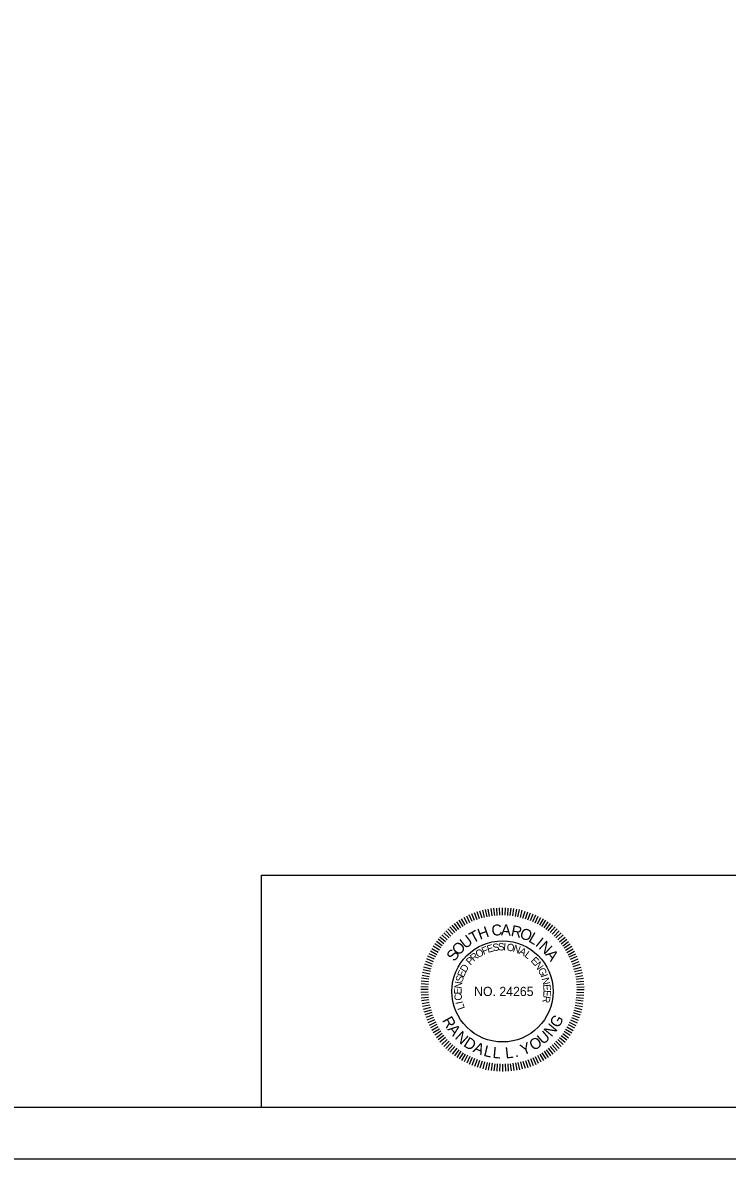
# Model space of a CAD drawing. Extents: x 8134 to 11793, y 3225 to 13425.
# Drawn here: x 10879 to 11221, y 5500 to 6050 of the extents above; entities that cross this region are included whole.
import ezdxf

# ---------------------------------------------------------------- set-up
doc = ezdxf.new("R2010")
doc.units = 0
for name, color, linetype in [('RD_SHT_Bndy', 7, 'Continuous'), ('RD_SHT_IplotShp', 7, 'Continuous'), ('RD_TX_PEShield', 7, 'Continuous')]:
    doc.layers.add(name, color=color, linetype=linetype)

msp = doc.modelspace()

# ---------------------------------------------------------------- linework, layer by layer
at = {"layer": 'RD_SHT_Bndy'}
for p, q in [((10995.01, 5637.45), (11757.6, 5637.45)), ((10995.01, 5525), (10995.01, 5637.45)), ((11760, 5500), (10000, 5500)), ((11760, 5500), (10000, 5500))]:
    msp.add_line(p, q, dxfattribs=at)
msp.add_lwpolyline([(10082.6, 6575), (11757.6, 6575), (11757.6, 5525), (10082.6, 5525)], close=True, dxfattribs=at)
at = {"layer": 'RD_SHT_IplotShp'}
msp.add_lwpolyline([(9981.4, 6600), (11777.4, 6600), (11777.4, 5500), (9981.4, 5500)], close=True, dxfattribs=at)
at = {"layer": 'RD_TX_PEShield'}
for p, q in [((11105.5, 5617.56), (11104.88, 5621.06)), ((11105.5, 5617.56), (11104.88, 5621.06)), ((11106.74, 5617.75), (11106.24, 5621.28)), ((11106.74, 5617.75), (11106.24, 5621.28)), ((11107.98, 5617.95), (11107.61, 5621.49)), ((11107.98, 5617.95), (11107.61, 5621.49)), ((11109.24, 5618.02), (11108.99, 5621.56)), ((11109.24, 5618.02), (11108.99, 5621.56)), ((11110.49, 5618.08), (11110.37, 5621.64)), ((11110.49, 5618.08), (11110.37, 5621.64)), ((11111.75, 5618.15), (11111.75, 5621.71)), ((11111.75, 5618.15), (11111.75, 5621.71)), ((11113.01, 5618.08), (11113.13, 5621.64)), ((11113.01, 5618.08), (11113.13, 5621.64)), ((11114.26, 5618.02), (11114.51, 5621.56)), ((11114.26, 5618.02), (11114.51, 5621.56)), ((11115.52, 5617.95), (11115.89, 5621.49)), ((11115.52, 5617.95), (11115.89, 5621.49)), ((11116.76, 5617.75), (11117.26, 5621.28)), ((11116.76, 5617.75), (11117.26, 5621.28)), ((11118, 5617.56), (11118.62, 5621.06)), ((11118, 5617.56), (11118.62, 5621.06)), ((11092.67, 5612.63), (11090.79, 5615.65)), ((11092.67, 5612.63), (11090.79, 5615.65)), ((11093.73, 5613.32), (11091.95, 5616.4)), ((11093.73, 5613.32), (11091.95, 5616.4)), ((11094.85, 5613.89), (11093.18, 5617.03)), ((11094.85, 5613.89), (11093.18, 5617.03)), ((11095.97, 5614.46), (11094.41, 5617.66)), ((11095.97, 5614.46), (11094.41, 5617.66)), ((11097.09, 5615.03), (11095.64, 5618.29)), ((11097.09, 5615.03), (11095.64, 5618.29)), ((11098.26, 5615.48), (11096.93, 5618.78)), ((11098.26, 5615.48), (11096.93, 5618.78)), ((11099.44, 5615.93), (11098.22, 5619.28)), ((11099.44, 5615.93), (11098.22, 5619.28)), ((11100.61, 5616.38), (11099.51, 5619.77)), ((11100.61, 5616.38), (11099.51, 5619.77)), ((11101.83, 5616.71), (11100.85, 5620.13)), ((11101.83, 5616.71), (11100.85, 5620.13)), ((11103.04, 5617.04), (11102.18, 5620.49)), ((11103.04, 5617.04), (11102.18, 5620.49)), ((11104.26, 5617.36), (11103.52, 5620.84)), ((11104.26, 5617.36), (11103.52, 5620.84)), ((11119.24, 5617.36), (11119.98, 5620.84)), ((11119.24, 5617.36), (11119.98, 5620.84)), ((11119.24, 5617.36), (11119.98, 5620.84)), ((11120.46, 5617.04), (11121.32, 5620.49)), ((11120.46, 5617.04), (11121.32, 5620.49)), ((11120.46, 5617.04), (11121.32, 5620.49)), ((11121.67, 5616.71), (11122.65, 5620.13)), ((11121.67, 5616.71), (11122.65, 5620.13)), ((11121.67, 5616.71), (11122.65, 5620.13)), ((11122.89, 5616.38), (11123.99, 5619.77)), ((11122.89, 5616.38), (11123.99, 5619.77)), ((11122.89, 5616.38), (11123.99, 5619.77)), ((11124.06, 5615.93), (11125.28, 5619.28)), ((11124.06, 5615.93), (11125.28, 5619.28)), ((11124.06, 5615.93), (11125.28, 5619.28)), ((11125.24, 5615.48), (11126.57, 5618.78)), ((11125.24, 5615.48), (11126.57, 5618.78)), ((11125.24, 5615.48), (11126.57, 5618.78)), ((11126.41, 5615.03), (11127.86, 5618.29)), ((11126.41, 5615.03), (11127.86, 5618.29)), ((11126.41, 5615.03), (11127.86, 5618.29)), ((11127.53, 5614.46), (11129.09, 5617.66)), ((11127.53, 5614.46), (11129.09, 5617.66)), ((11127.53, 5614.46), (11129.09, 5617.66)), ((11128.65, 5613.89), (11130.32, 5617.03)), ((11128.65, 5613.89), (11130.32, 5617.03)), ((11128.65, 5613.89), (11130.32, 5617.03)), ((11129.77, 5613.32), (11131.55, 5616.4)), ((11129.77, 5613.32), (11131.55, 5616.4)), ((11129.77, 5613.32), (11131.55, 5616.4)), ((11130.83, 5612.63), (11132.71, 5615.65)), ((11130.83, 5612.63), (11132.71, 5615.65)), ((11130.83, 5612.63), (11132.71, 5615.65)), ((11086.74, 5608), (11084.27, 5610.56)), ((11086.74, 5608), (11084.27, 5610.56)), ((11087.63, 5608.89), (11085.25, 5611.54)), ((11087.63, 5608.89), (11085.25, 5611.54)), ((11088.61, 5609.68), (11086.32, 5612.41)), ((11088.61, 5609.68), (11086.32, 5612.41)), ((11089.59, 5610.47), (11087.4, 5613.28)), ((11089.59, 5610.47), (11087.4, 5613.28)), ((11090.56, 5611.27), (11088.47, 5614.15)), ((11090.56, 5611.27), (11088.47, 5614.15)), ((11091.62, 5611.95), (11089.63, 5614.9)), ((11091.62, 5611.95), (11089.63, 5614.9)), ((11131.88, 5611.95), (11133.87, 5614.9)), ((11131.88, 5611.95), (11133.87, 5614.9)), ((11131.88, 5611.95), (11133.87, 5614.9)), ((11132.94, 5611.27), (11135.03, 5614.15)), ((11132.94, 5611.27), (11135.03, 5614.15)), ((11132.94, 5611.27), (11135.03, 5614.15)), ((11133.91, 5610.47), (11136.1, 5613.28)), ((11133.91, 5610.47), (11136.1, 5613.28)), ((11133.91, 5610.47), (11136.1, 5613.28)), ((11134.89, 5609.68), (11137.18, 5612.41)), ((11134.89, 5609.68), (11137.18, 5612.41)), ((11134.89, 5609.68), (11137.18, 5612.41)), ((11135.87, 5608.89), (11138.25, 5611.54)), ((11135.87, 5608.89), (11138.25, 5611.54)), ((11135.87, 5608.89), (11138.25, 5611.54)), ((11136.76, 5608), (11139.23, 5610.56)), ((11136.76, 5608), (11139.23, 5610.56)), ((11136.76, 5608), (11139.23, 5610.56)), ((11082.59, 5603.29), (11079.71, 5605.38)), ((11082.59, 5603.29), (11079.71, 5605.38)), ((11083.38, 5604.27), (11080.58, 5606.46)), ((11083.38, 5604.27), (11080.58, 5606.46)), ((11084.17, 5605.25), (11081.45, 5607.53)), ((11084.17, 5605.25), (11081.45, 5607.53)), ((11084.96, 5606.22), (11082.32, 5608.6)), ((11084.96, 5606.22), (11082.32, 5608.6)), ((11085.85, 5607.11), (11083.3, 5609.58)), ((11085.85, 5607.11), (11083.3, 5609.58)), ((11137.65, 5607.11), (11140.2, 5609.58)), ((11137.65, 5607.11), (11140.2, 5609.58)), ((11137.65, 5607.11), (11140.2, 5609.58)), ((11138.54, 5606.22), (11141.18, 5608.6)), ((11138.54, 5606.22), (11141.18, 5608.6)), ((11138.54, 5606.22), (11141.18, 5608.6)), ((11139.33, 5605.25), (11142.05, 5607.53)), ((11139.33, 5605.25), (11142.05, 5607.53)), ((11139.33, 5605.25), (11142.05, 5607.53)), ((11140.12, 5604.27), (11142.92, 5606.46)), ((11140.12, 5604.27), (11142.92, 5606.46)), ((11140.12, 5604.27), (11142.92, 5606.46)), ((11140.91, 5603.29), (11143.79, 5605.38)), ((11140.91, 5603.29), (11143.79, 5605.38)), ((11140.91, 5603.29), (11143.79, 5605.38)), ((11079.39, 5597.89), (11076.2, 5599.44)), ((11079.39, 5597.89), (11076.2, 5599.44)), ((11079.96, 5599.01), (11076.82, 5600.67)), ((11079.96, 5599.01), (11076.82, 5600.67)), ((11080.53, 5600.13), (11077.45, 5601.91)), ((11080.53, 5600.13), (11077.45, 5601.91)), ((11081.22, 5601.18), (11078.2, 5603.07)), ((11081.22, 5601.18), (11078.2, 5603.07)), ((11081.9, 5602.24), (11078.96, 5604.22)), ((11081.9, 5602.24), (11078.96, 5604.22)), ((11141.6, 5602.24), (11144.54, 5604.22)), ((11141.6, 5602.24), (11144.54, 5604.22)), ((11141.6, 5602.24), (11144.54, 5604.22)), ((11142.28, 5601.18), (11145.3, 5603.07)), ((11142.28, 5601.18), (11145.3, 5603.07)), ((11142.28, 5601.18), (11145.3, 5603.07)), ((11142.97, 5600.13), (11146.05, 5601.91)), ((11142.97, 5600.13), (11146.05, 5601.91)), ((11142.97, 5600.13), (11146.05, 5601.91)), ((11143.54, 5599.01), (11146.68, 5600.67)), ((11143.54, 5599.01), (11146.68, 5600.67)), ((11143.54, 5599.01), (11146.68, 5600.67)), ((11144.11, 5597.89), (11147.3, 5599.44)), ((11144.11, 5597.89), (11147.3, 5599.44)), ((11144.11, 5597.89), (11147.3, 5599.44)), ((11077.47, 5593.24), (11074.08, 5594.34)), ((11077.47, 5593.24), (11074.08, 5594.34)), ((11077.92, 5594.42), (11074.58, 5595.63)), ((11077.92, 5594.42), (11074.58, 5595.63)), ((11078.37, 5595.59), (11075.07, 5596.92)), ((11078.37, 5595.59), (11075.07, 5596.92)), ((11078.82, 5596.76), (11075.57, 5598.21)), ((11078.82, 5596.76), (11075.57, 5598.21)), ((11144.68, 5596.76), (11147.93, 5598.21)), ((11144.68, 5596.76), (11147.93, 5598.21)), ((11144.68, 5596.76), (11147.93, 5598.21)), ((11145.13, 5595.59), (11148.43, 5596.92)), ((11145.13, 5595.59), (11148.43, 5596.92)), ((11145.13, 5595.59), (11148.43, 5596.92)), ((11145.58, 5594.42), (11148.92, 5595.63)), ((11145.58, 5594.42), (11148.92, 5595.63)), ((11145.58, 5594.42), (11148.92, 5595.63)), ((11146.03, 5593.24), (11149.42, 5594.34)), ((11146.03, 5593.24), (11149.42, 5594.34)), ((11146.03, 5593.24), (11149.42, 5594.34)), ((11076.3, 5588.36), (11072.79, 5588.97)), ((11076.3, 5588.36), (11072.79, 5588.97)), ((11076.49, 5589.6), (11073.01, 5590.34)), ((11076.49, 5589.6), (11073.01, 5590.34)), ((11076.82, 5590.81), (11073.37, 5591.67)), ((11076.82, 5590.81), (11073.37, 5591.67)), ((11077.14, 5592.03), (11073.73, 5593.01)), ((11077.14, 5592.03), (11073.73, 5593.01)), ((11146.36, 5592.03), (11149.77, 5593.01)), ((11146.36, 5592.03), (11149.77, 5593.01)), ((11146.36, 5592.03), (11149.77, 5593.01)), ((11146.68, 5590.81), (11150.13, 5591.67)), ((11146.68, 5590.81), (11150.13, 5591.67)), ((11146.68, 5590.81), (11150.13, 5591.67)), ((11147.01, 5589.6), (11150.49, 5590.34)), ((11147.01, 5589.6), (11150.49, 5590.34)), ((11147.01, 5589.6), (11150.49, 5590.34)), ((11147.2, 5588.36), (11150.71, 5588.97)), ((11147.2, 5588.36), (11150.71, 5588.97)), ((11147.2, 5588.36), (11150.71, 5588.97)), ((11075.77, 5583.36), (11072.22, 5583.48)), ((11075.77, 5583.36), (11072.22, 5583.48)), ((11075.84, 5584.62), (11072.29, 5584.86)), ((11075.84, 5584.62), (11072.29, 5584.86)), ((11075.9, 5585.87), (11072.36, 5586.24)), ((11075.9, 5585.87), (11072.36, 5586.24)), ((11076.1, 5587.11), (11072.58, 5587.61)), ((11076.1, 5587.11), (11072.58, 5587.61)), ((11147.4, 5587.11), (11150.92, 5587.61)), ((11147.4, 5587.11), (11150.92, 5587.61)), ((11147.4, 5587.11), (11150.92, 5587.61)), ((11147.6, 5585.87), (11151.14, 5586.24)), ((11147.6, 5585.87), (11151.14, 5586.24)), ((11147.6, 5585.87), (11151.14, 5586.24)), ((11147.66, 5584.62), (11151.21, 5584.86)), ((11147.66, 5584.62), (11151.21, 5584.86)), ((11147.66, 5584.62), (11151.21, 5584.86)), ((11147.73, 5583.36), (11151.28, 5583.48)), ((11147.73, 5583.36), (11151.28, 5583.48)), ((11147.73, 5583.36), (11151.28, 5583.48)), ((11075.7, 5582.1), (11072.14, 5582.1)), ((11075.7, 5582.1), (11072.14, 5582.1)), ((11075.77, 5580.85), (11072.22, 5580.72)), ((11075.77, 5580.85), (11072.22, 5580.72)), ((11075.84, 5579.59), (11072.29, 5579.34)), ((11075.84, 5579.59), (11072.29, 5579.34)), ((11075.9, 5578.34), (11072.36, 5577.96)), ((11075.9, 5578.34), (11072.36, 5577.96)), ((11076.1, 5577.09), (11072.58, 5576.6)), ((11076.1, 5577.09), (11072.58, 5576.6)), ((11147.27, 5577.11), (11150.78, 5576.62)), ((11147.27, 5577.11), (11150.78, 5576.62)), ((11147.4, 5578.36), (11150.92, 5577.99)), ((11147.4, 5578.36), (11150.92, 5577.99)), ((11147.53, 5579.6), (11151.07, 5579.35)), ((11147.53, 5579.6), (11151.07, 5579.35)), ((11147.66, 5580.85), (11151.21, 5580.73)), ((11147.66, 5580.85), (11151.21, 5580.73)), ((11147.79, 5582.1), (11151.35, 5582.1)), ((11147.79, 5582.1), (11151.35, 5582.1)), ((11147.79, 5582.1), (11151.35, 5582.1)), ((11076.3, 5575.85), (11072.79, 5575.24)), ((11076.3, 5575.85), (11072.79, 5575.24)), ((11076.49, 5574.61), (11073.01, 5573.87)), ((11076.49, 5574.61), (11073.01, 5573.87)), ((11076.82, 5573.39), (11073.37, 5572.53)), ((11076.82, 5573.39), (11073.37, 5572.53)), ((11077.14, 5572.18), (11073.73, 5571.2)), ((11077.14, 5572.18), (11073.73, 5571.2)), ((11146.36, 5572.18), (11149.77, 5571.2)), ((11146.36, 5572.18), (11149.77, 5571.2)), ((11146.68, 5573.39), (11150.13, 5572.53)), ((11146.68, 5573.39), (11150.13, 5572.53)), ((11147.01, 5574.61), (11150.49, 5573.87)), ((11147.01, 5574.61), (11150.49, 5573.87)), ((11147.14, 5575.86), (11150.63, 5575.25)), ((11147.14, 5575.86), (11150.63, 5575.25)), ((11077.47, 5570.97), (11074.08, 5569.87)), ((11077.92, 5569.79), (11074.58, 5568.57)), ((11077.92, 5569.79), (11074.58, 5568.57)), ((11078.37, 5568.62), (11075.07, 5567.29)), ((11078.37, 5568.62), (11075.07, 5567.29)), ((11078.82, 5567.44), (11075.57, 5566)), ((11078.82, 5567.44), (11075.57, 5566)), ((11079.39, 5566.32), (11076.2, 5564.76)), ((11079.39, 5566.32), (11076.2, 5564.76)), ((11144.11, 5566.32), (11147.3, 5564.76)), ((11144.11, 5566.32), (11147.3, 5564.76)), ((11144.68, 5567.44), (11147.93, 5566)), ((11144.68, 5567.44), (11147.93, 5566)), ((11145.13, 5568.62), (11148.43, 5567.29)), ((11145.13, 5568.62), (11148.43, 5567.29)), ((11145.58, 5569.79), (11148.92, 5568.57)), ((11145.58, 5569.79), (11148.92, 5568.57)), ((11146.03, 5570.97), (11149.42, 5569.87)), ((11146.03, 5570.97), (11149.42, 5569.87)), ((11079.96, 5565.2), (11076.82, 5563.53)), ((11079.96, 5565.2), (11076.82, 5563.53)), ((11080.53, 5564.08), (11077.45, 5562.3)), ((11080.53, 5564.08), (11077.45, 5562.3)), ((11081.22, 5563.03), (11078.2, 5561.14)), ((11081.22, 5563.03), (11078.2, 5561.14)), ((11081.9, 5561.97), (11078.96, 5559.98)), ((11081.9, 5561.97), (11078.96, 5559.98)), ((11082.59, 5560.92), (11079.71, 5558.82)), ((11082.59, 5560.92), (11079.71, 5558.82)), ((11140.91, 5560.92), (11143.79, 5558.82)), ((11140.91, 5560.92), (11143.79, 5558.82)), ((11141.6, 5561.97), (11144.54, 5559.98)), ((11141.6, 5561.97), (11144.54, 5559.98)), ((11142.28, 5563.03), (11145.3, 5561.14)), ((11142.28, 5563.03), (11145.3, 5561.14)), ((11142.97, 5564.08), (11146.05, 5562.3)), ((11142.97, 5564.08), (11146.05, 5562.3)), ((11143.54, 5565.2), (11146.68, 5563.53)), ((11143.54, 5565.2), (11146.68, 5563.53)), ((11083.38, 5559.94), (11080.58, 5557.75)), ((11083.38, 5559.94), (11080.58, 5557.75)), ((11084.17, 5558.96), (11081.45, 5556.68)), ((11084.17, 5558.96), (11081.45, 5556.68)), ((11084.96, 5557.99), (11082.32, 5555.6)), ((11084.96, 5557.99), (11082.32, 5555.6)), ((11085.85, 5557.1), (11083.3, 5554.63)), ((11085.85, 5557.1), (11083.3, 5554.63)), ((11086.74, 5556.21), (11084.27, 5553.65)), ((11086.74, 5556.21), (11084.27, 5553.65)), ((11087.63, 5555.32), (11085.25, 5552.67)), ((11087.63, 5555.32), (11085.25, 5552.67)), ((11135.87, 5555.32), (11138.25, 5552.67)), ((11136.76, 5556.21), (11139.23, 5553.65)), ((11136.76, 5556.21), (11139.23, 5553.65)), ((11137.65, 5557.1), (11140.2, 5554.63)), ((11137.65, 5557.1), (11140.2, 5554.63)), ((11138.54, 5557.99), (11141.18, 5555.6)), ((11138.54, 5557.99), (11141.18, 5555.6)), ((11139.33, 5558.96), (11142.05, 5556.68)), ((11139.33, 5558.96), (11142.05, 5556.68)), ((11140.12, 5559.94), (11142.92, 5557.75)), ((11140.12, 5559.94), (11142.92, 5557.75)), ((11088.61, 5554.53), (11086.32, 5551.8)), ((11088.61, 5554.53), (11086.32, 5551.8)), ((11089.59, 5553.73), (11087.4, 5550.93)), ((11089.59, 5553.73), (11087.4, 5550.93)), ((11090.56, 5552.94), (11088.47, 5550.06)), ((11090.56, 5552.94), (11088.47, 5550.06)), ((11091.62, 5552.26), (11089.63, 5549.31)), ((11091.62, 5552.26), (11089.63, 5549.31)), ((11092.67, 5551.57), (11090.79, 5548.56)), ((11092.67, 5551.57), (11090.79, 5548.56)), ((11093.73, 5550.89), (11091.95, 5547.81)), ((11093.73, 5550.89), (11091.95, 5547.81)), ((11094.85, 5550.32), (11093.18, 5547.18)), ((11094.85, 5550.32), (11093.18, 5547.18)), ((11095.97, 5549.75), (11094.41, 5546.55)), ((11095.97, 5549.75), (11094.41, 5546.55)), ((11127.53, 5549.75), (11129.09, 5546.55)), ((11127.53, 5549.75), (11129.09, 5546.55)), ((11128.65, 5550.32), (11130.32, 5547.18)), ((11128.65, 5550.32), (11130.32, 5547.18)), ((11129.77, 5550.89), (11131.55, 5547.81)), ((11129.77, 5550.89), (11131.55, 5547.81)), ((11130.83, 5551.57), (11132.71, 5548.56)), ((11130.83, 5551.57), (11132.71, 5548.56)), ((11131.88, 5552.26), (11133.87, 5549.31)), ((11131.88, 5552.26), (11133.87, 5549.31)), ((11132.94, 5552.94), (11135.03, 5550.06)), ((11132.94, 5552.94), (11135.03, 5550.06)), ((11133.91, 5553.73), (11136.1, 5550.93)), ((11133.91, 5553.73), (11136.1, 5550.93)), ((11134.89, 5554.53), (11137.18, 5551.8)), ((11134.89, 5554.53), (11137.18, 5551.8)), ((11097.09, 5549.18), (11095.64, 5545.92)), ((11097.09, 5549.18), (11095.64, 5545.92)), ((11098.26, 5548.72), (11096.93, 5545.43)), ((11098.26, 5548.72), (11096.93, 5545.43)), ((11099.44, 5548.27), (11098.22, 5544.93)), ((11099.44, 5548.27), (11098.22, 5544.93)), ((11100.61, 5547.82), (11099.51, 5544.44)), ((11100.61, 5547.82), (11099.51, 5544.44)), ((11101.83, 5547.5), (11100.85, 5544.08)), ((11101.83, 5547.5), (11100.85, 5544.08)), ((11103.04, 5547.17), (11102.18, 5543.72)), ((11103.04, 5547.17), (11102.18, 5543.72)), ((11104.26, 5546.85), (11103.52, 5543.36)), ((11104.26, 5546.85), (11103.52, 5543.36)), ((11105.5, 5546.65), (11104.88, 5543.15)), ((11105.5, 5546.65), (11104.88, 5543.15)), ((11106.74, 5546.45), (11106.24, 5542.93)), ((11106.74, 5546.45), (11106.24, 5542.93)), ((11107.98, 5546.26), (11107.61, 5542.72)), ((11107.98, 5546.26), (11107.61, 5542.72)), ((11109.24, 5546.19), (11108.99, 5542.64)), ((11109.24, 5546.19), (11108.99, 5542.64)), ((11110.49, 5546.12), (11110.37, 5542.57)), ((11110.49, 5546.12), (11110.37, 5542.57)), ((11111.75, 5546.06), (11111.75, 5542.5)), ((11111.75, 5546.06), (11111.75, 5542.5)), ((11113.01, 5546.12), (11113.13, 5542.57)), ((11113.01, 5546.12), (11113.13, 5542.57)), ((11114.26, 5546.19), (11114.51, 5542.64)), ((11114.26, 5546.19), (11114.51, 5542.64)), ((11115.52, 5546.26), (11115.89, 5542.72)), ((11115.52, 5546.26), (11115.89, 5542.72)), ((11116.76, 5546.45), (11117.26, 5542.93)), ((11116.76, 5546.45), (11117.26, 5542.93)), ((11118, 5546.65), (11118.62, 5543.15)), ((11118, 5546.65), (11118.62, 5543.15)), ((11119.24, 5546.85), (11119.98, 5543.36)), ((11119.24, 5546.85), (11119.98, 5543.36)), ((11120.46, 5547.17), (11121.32, 5543.72)), ((11120.46, 5547.17), (11121.32, 5543.72)), ((11121.67, 5547.5), (11122.65, 5544.08)), ((11121.67, 5547.5), (11122.65, 5544.08)), ((11122.89, 5547.82), (11123.99, 5544.44)), ((11122.89, 5547.82), (11123.99, 5544.44)), ((11124.06, 5548.27), (11125.28, 5544.93)), ((11124.06, 5548.27), (11125.28, 5544.93)), ((11125.24, 5548.72), (11126.57, 5545.43)), ((11125.24, 5548.72), (11126.57, 5545.43)), ((11126.41, 5549.18), (11127.86, 5545.92)), ((11126.41, 5549.18), (11127.86, 5545.92))]:
    msp.add_line(p, q, dxfattribs=at)
msp.add_circle((11111.75, 5581.23), 24.48, dxfattribs=at)

# ---------------------------------------------------------------- texts
for s, height, rotation, p in [('T', 5.34, 28.0947, (11097.41, 5604.34)), ('H', 5.34, 19.9102, (11100.85, 5606.15)), ('C', 5.34, 6.8832, (11106.74, 5607.96)), ('A', 5.34, 357.9448, (11110.96, 5608.42)), ('R', 5.34, 348.267, (11115.54, 5608.16)), ('O', 5.34, 339.3286, (11119.68, 5607.25)), ('O', 5.34, 47.4504, (11090.56, 5598.28)), ('U', 5.34, 37.7726, (11093.73, 5601.6)), ('S', 3.56, 8.6909, (11107.24, 5600.61)), ('S', 3.56, 1.79, (11109.6, 5601.02)), ('I', 3.56, 354.889, (11111.99, 5601.13)), ('L', 5.34, 329.6507, (11123.94, 5605.54)), ('I', 5.34, 321.4663, (11127.28, 5603.56)), ('N', 5.34, 317.0007, (11128.97, 5602.28)), ('S', 5.34, 54.9027, (11088.53, 5595.39)), ('R', 3.56, 39.8902, (11097.85, 5595.47)), ('O', 3.56, 31.7869, (11099.99, 5597.29)), ('F', 3.56, 23.0853, (11102.56, 5598.88)), ('E', 3.56, 16.1843, (11104.75, 5599.86)), ('O', 3.56, 350.4045, (11113.55, 5601.05)), ('N', 3.56, 341.7029, (11116.53, 5600.55)), ('A', 3.56, 333.0013, (11119.4, 5599.6)), ('L', 3.56, 324.2997, (11122.09, 5598.24)), ('A', 5.34, 307.3229, (11132.27, 5599.09)), ('D', 3.56, 59.074, (11093.94, 5590.11)), ('P', 3.56, 46.7912, (11096.24, 5593.7)), ('E', 3.56, 313.2251, (11125.16, 5595.93)), ('N', 3.56, 305.7317, (11126.97, 5594.06)), ('S', 3.56, 73.4683, (11092.29, 5585.41)), ('E', 3.56, 66.5674, (11092.93, 5587.71)), ('G', 3.56, 297.0301, (11128.73, 5591.61)), ('I', 3.56, 288.3285, (11130.11, 5588.92)), ('E', 3.56, 89.6633, (11091.89, 5579.81)), ('N', 3.56, 82.17, (11091.88, 5582.41)), ('N', 3.56, 283.8441, (11130.65, 5587.46)), ('E', 3.56, 275.1424, (11131.38, 5584.53)), ('C', 3.56, 97.7667, (11092.29, 5577.03)), ('R', 3.56, 260.1557, (11131.57, 5579.34)), ('E', 3.56, 267.6491, (11131.64, 5581.94)), ('I', 3.56, 102.2511, (11092.68, 5575.52)), ('L', 3.56, 109.7445, (11093.59, 5573.08)), ('R', 5.34, 299.1493, (11082.35, 5567.25)), ('G', 5.34, 60.1113, (11138.86, 5563.2)), ('A', 5.34, 308.0877, (11084.88, 5562.85)), ('N', 5.34, 317.7655, (11088.35, 5558.6)), ('U', 5.34, 40.7556, (11131.35, 5555.24)), ('N', 5.34, 50.4335, (11135.44, 5558.9)), ('D', 5.34, 327.4433, (11092.48, 5554.99)), ('A', 5.34, 337.1212, (11097.17, 5552.12)), ('L', 5.34, 346.799, (11102.27, 5550.08)), ('Y', 5.34, 21.4, (11121.63, 5550.21)), ('O', 5.34, 31.0778, (11126.71, 5552.31)), ('L', 5.34, 354.9835, (11106.8, 5549.05)), ('L', 5.34, 6.5171, (11113.33, 5548.71)), ('.', 5.34, 14.7016, (11117.95, 5549.27))]:
    msp.add_text(s, height=height, rotation=rotation, dxfattribs=at).set_placement(p)
msp.add_text('NO. 24265', height=4.45, dxfattribs=at).set_placement((11098, 5579))

doc.saveas('drawing.dxf')
